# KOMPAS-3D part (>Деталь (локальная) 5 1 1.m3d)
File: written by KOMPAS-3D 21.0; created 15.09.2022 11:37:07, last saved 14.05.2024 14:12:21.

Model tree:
1. Эскиз:1

Referenced files in C:\Program Files\Ascon\Libs\EasySteel\: Rolled metal.kle, StandartSolutions.kle, DSTVProperties.lpt
Referenced files in W:\Шаблоны чертежей\: Констр. чертеж А3 гориз. перв. лист.cdt
Referenced files in C:\Program Files\Ascon\Libs\EasySteel\BeltEndings\: 
Referenced files in C:\Program Files\Ascon\Libs\EasySteel\Punctures\: 
Referenced files in C:\Program Files\Ascon\Libs\EasySteel\Insulations\: 
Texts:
  Уголок равнополочный по ГОСТ 8509-93 (Спец)
  config2DpacketName
  config2DstdSizeID
  Констр. чертеж А3 гориз. перв. лист.cdt
  Болт ГОСТ 22353-77
  Шайба ГОСТ 22355-77
  Гайка ГОСТ 22354-77
  Нормальная пружинная шайба ГОСТ 6402-70 (исп. 1)
  SeaRox SL 436
  Сталь 09Г2С ГОСТ 19281-2014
